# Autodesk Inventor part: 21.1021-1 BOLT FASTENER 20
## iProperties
Created: 2006-12
Part Number: 21.1021-1 BOLT FASTENER 20
Document SubType Name: Modeling
Designer: Andy Moles
Material: Steel
Density: 7.85 g/cm^3
Author: Andy Moles
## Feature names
1. Extrusion1
2. Extrusion2
3. Extrusion3
4. Chamfer1
